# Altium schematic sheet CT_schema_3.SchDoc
size 208 x 169 mm
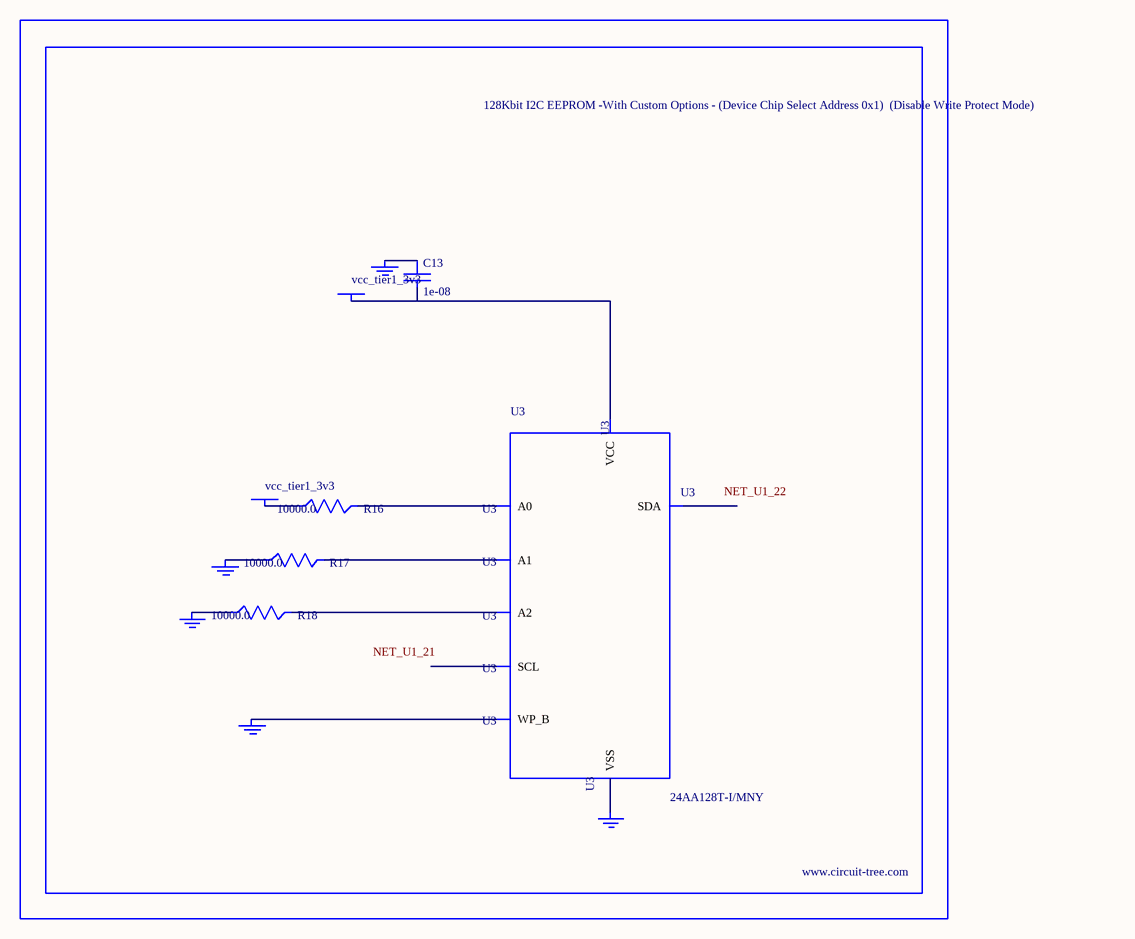
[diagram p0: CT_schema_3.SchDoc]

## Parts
BORDER2  (no value)
C13  1e-08  [C0402]
GND_INSTANCE_2_0  (no value)
GND_INSTANCE_2_1  (no value)
GND_INSTANCE_2_2  (no value)
GND_INSTANCE_2_3  (no value)
GND_INSTANCE_2_4  (no value)
POWER_INSTANCE_2_0  vcc_tier1_3v3
POWER_INSTANCE_2_1  vcc_tier1_3v3
R16  10000.0  [R0603]
R17  10000.0  [R0603]
R18  10000.0  [R0603]
U3  24AA128T-I/MNY  [TDFN-8/6MM]

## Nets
NetC13_1: C13.1 GND_INSTANCE_2_3.0(GND)
NetC13_2: C13.2 POWER_INSTANCE_2_1.0(PWR) U3.8(VCC)
NetGND_INSTANCE_2_0_0: GND_INSTANCE_2_0.0(GND) R17.1
NetGND_INSTANCE_2_1_0: GND_INSTANCE_2_1.0(GND) R18.1
NetGND_INSTANCE_2_2_0: GND_INSTANCE_2_2.0(GND) U3.7(WP_B)
NetGND_INSTANCE_2_4_0: GND_INSTANCE_2_4.0(GND) U3.4(VSS)
NetPOWER_INSTANCE_2_0_0: POWER_INSTANCE_2_0.0(PWR) R16.1
NetR16_2: R16.2 U3.1(A0)
NetR17_2: R17.2 U3.2(A1)
NetR18_2: R18.2 U3.3(A2)

Not connected (* = marked no-connect by the designer): U3 5(SDA) 6(SCL)

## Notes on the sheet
- Labels drawn without touching a wire or pin: NET_U1_21, NET_U1_22

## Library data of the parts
BORDER2 = BORDER_PAGE2
C13 = C0402C103K3RAC
GND_INSTANCE_2_0-GND_INSTANCE_2_4 = GND
POWER_INSTANCE_2_0 POWER_INSTANCE_2_1 = PWR
R16-R18 = RC0603JR-0710KL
